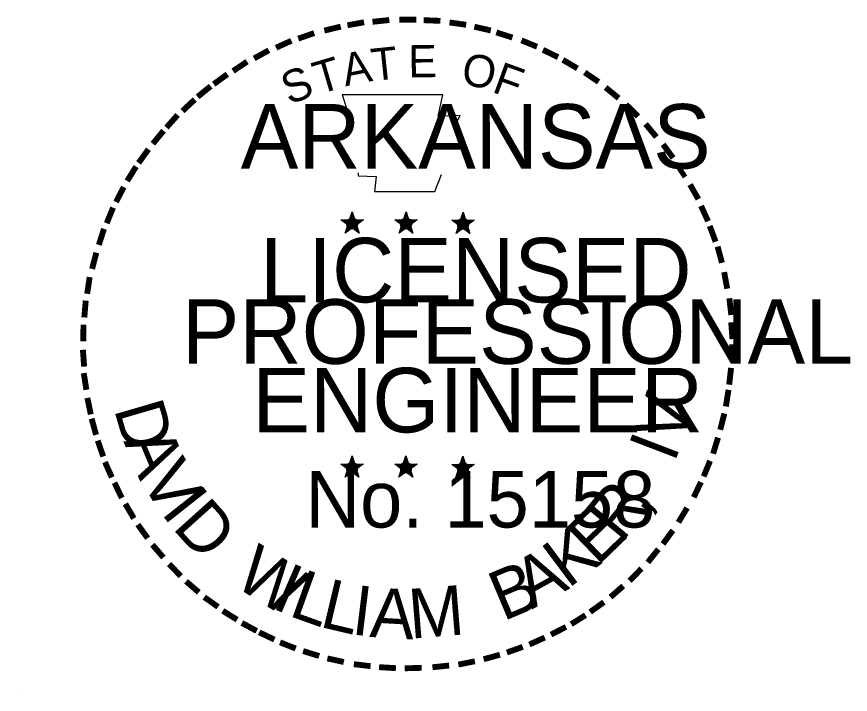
# Model space of a CAD drawing. Extents: x 28704 to 32542, y 50360 to 59122.
# Drawn here: x 30525.5 to 30658.7, y 58979.9 to 59088.2 of the extents above; entities that cross this region are included whole.
import ezdxf

# ---------------------------------------------------------------- set-up
doc = ezdxf.new("R2010")
doc.units = 0
doc.layers.add('R_Border Prem', color=7, linetype='Continuous')
doc.layers.add('R_Contours', color=7, linetype='Continuous')

msp = doc.modelspace()

# ---------------------------------------------------------------- linework, layer by layer
at = {"layer": 'R_Border Prem'}
for p, q in [((30579.13, 59057.02), (30578.92, 59055.72)), ((30579.13, 59055.14), (30579.13, 59057.02)), ((30579.13, 59057.02), (30579.38, 59055.73)), ((30587.74, 59057.02), (30587.53, 59055.72)), ((30587.74, 59055.14), (30587.74, 59057.02)), ((30587.74, 59057.02), (30587.99, 59055.73)), ((30596.84, 59056.96), (30596.63, 59055.66)), ((30596.84, 59055.08), (30596.84, 59056.96)), ((30596.84, 59056.96), (30597.09, 59055.67)), ((30577.33, 59055.71), (30579.13, 59055.14)), ((30577.33, 59055.71), (30578.64, 59055.48)), ((30577.33, 59055.71), (30578.55, 59055.08)), ((30578.02, 59053.61), (30579.13, 59055.14)), ((30578.02, 59053.61), (30578.67, 59054.87)), ((30578.02, 59053.61), (30579.12, 59054.73)), ((30580.23, 59053.61), (30579.12, 59054.71)), ((30580.92, 59055.71), (30579.13, 59055.14)), ((30580.23, 59053.61), (30579.13, 59055.14)), ((30580.92, 59055.71), (30579.44, 59055.46)), ((30580.23, 59053.61), (30579.52, 59055.11)), ((30580.92, 59055.71), (30579.87, 59055.18)), ((30585.94, 59055.71), (30587.74, 59055.14)), ((30585.94, 59055.71), (30587.25, 59055.48)), ((30585.94, 59055.71), (30587.16, 59055.08)), ((30586.63, 59053.61), (30587.74, 59055.14)), ((30586.63, 59053.61), (30587.28, 59054.87)), ((30586.63, 59053.61), (30587.73, 59054.73)), ((30588.84, 59053.61), (30587.73, 59054.71)), ((30589.53, 59055.71), (30587.74, 59055.14)), ((30588.84, 59053.61), (30587.74, 59055.14)), ((30589.53, 59055.71), (30588.06, 59055.46)), ((30588.84, 59053.61), (30588.13, 59055.11)), ((30589.53, 59055.71), (30588.48, 59055.18)), ((30595.04, 59055.65), (30596.84, 59055.08)), ((30595.04, 59055.65), (30596.34, 59055.42)), ((30595.04, 59055.65), (30596.26, 59055.02)), ((30595.72, 59053.55), (30596.84, 59055.08)), ((30595.72, 59053.55), (30596.37, 59054.8)), ((30595.72, 59053.55), (30596.83, 59054.66)), ((30597.94, 59053.55), (30596.83, 59054.65)), ((30598.63, 59055.65), (30596.84, 59055.08)), ((30597.94, 59053.55), (30596.84, 59055.08)), ((30598.63, 59055.65), (30597.15, 59055.4)), ((30597.94, 59053.55), (30597.23, 59055.05)), ((30598.63, 59055.65), (30597.57, 59055.12)), ((30579.11, 59017.97), (30578.9, 59016.67)), ((30579.11, 59016.09), (30579.11, 59017.97)), ((30579.11, 59017.97), (30579.36, 59016.68)), ((30587.72, 59017.97), (30587.5, 59016.67)), ((30587.72, 59016.09), (30587.72, 59017.97)), ((30587.72, 59017.97), (30587.97, 59016.68)), ((30596.83, 59017.92), (30596.62, 59016.62)), ((30596.83, 59016.04), (30596.83, 59017.92)), ((30596.83, 59017.92), (30597.08, 59016.63)), ((30577.31, 59016.66), (30579.11, 59016.09)), ((30577.31, 59016.66), (30578.61, 59016.43)), ((30577.31, 59016.66), (30578.53, 59016.03)), ((30578, 59014.56), (30579.11, 59016.09)), ((30578, 59014.56), (30578.65, 59015.82)), ((30580.9, 59016.66), (30579.11, 59016.09)), ((30580.21, 59014.56), (30579.11, 59016.09)), ((30580.9, 59016.66), (30579.42, 59016.41)), ((30580.21, 59014.56), (30579.5, 59016.06)), ((30580.9, 59016.66), (30579.85, 59016.14)), ((30585.92, 59016.66), (30587.72, 59016.09)), ((30585.92, 59016.66), (30587.22, 59016.43)), ((30585.92, 59016.66), (30587.14, 59016.03)), ((30586.6, 59014.56), (30587.72, 59016.09)), ((30586.6, 59014.56), (30587.25, 59015.82)), ((30589.5, 59016.66), (30587.72, 59016.09)), ((30588.81, 59014.56), (30587.72, 59016.09)), ((30589.5, 59016.66), (30588.03, 59016.41)), ((30588.81, 59014.56), (30588.11, 59016.06)), ((30589.5, 59016.66), (30588.45, 59016.14)), ((30595.03, 59016.61), (30596.83, 59016.04)), ((30595.03, 59016.61), (30596.33, 59016.38)), ((30595.03, 59016.61), (30596.25, 59015.98)), ((30595.71, 59014.51), (30596.83, 59016.04)), ((30598.62, 59016.61), (30596.83, 59016.04)), ((30597.92, 59014.51), (30596.83, 59016.04)), ((30598.62, 59016.61), (30597.14, 59016.36)), ((30597.92, 59014.51), (30597.22, 59016.01)), ((30598.62, 59016.61), (30597.56, 59016.09)), ((30578, 59014.56), (30579.1, 59015.68)), ((30580.21, 59014.56), (30579.1, 59015.66)), ((30586.6, 59014.56), (30587.71, 59015.68)), ((30588.81, 59014.56), (30587.71, 59015.66)), ((30595.71, 59014.51), (30596.36, 59015.77)), ((30595.71, 59014.51), (30596.82, 59015.63)), ((30597.92, 59014.51), (30596.82, 59015.61))]:
    msp.add_line(p, q, dxfattribs=at)
for points in [[(30577.54, 59075.71), (30578.93, 59071.44)], [(30595.65, 59070.95), (30596.38, 59072.42), (30592.85, 59072.29), (30593.61, 59075.71), (30577.54, 59075.71)], [(30580.08, 59063.21), (30580.08, 59062.76), (30582.98, 59062.67), (30582.7, 59060.23), (30592.35, 59060.23), (30593.38, 59062.99)], [(30579.13, 59057.02), (30580.23, 59053.61), (30577.33, 59055.71), (30580.92, 59055.71), (30578.02, 59053.61), (30579.13, 59057.02)], [(30587.74, 59057.02), (30588.84, 59053.61), (30585.94, 59055.71), (30589.53, 59055.71), (30586.63, 59053.61), (30587.74, 59057.02)], [(30596.84, 59056.96), (30597.94, 59053.55), (30595.04, 59055.65), (30598.63, 59055.65), (30595.72, 59053.55), (30596.84, 59056.96)], [(30579.11, 59017.97), (30580.21, 59014.56), (30577.31, 59016.66), (30580.9, 59016.66), (30578, 59014.56), (30579.11, 59017.97)], [(30587.72, 59017.97), (30588.81, 59014.56), (30585.92, 59016.66), (30589.5, 59016.66), (30586.6, 59014.56), (30587.72, 59017.97)], [(30596.83, 59017.92), (30597.92, 59014.51), (30595.03, 59016.61), (30598.62, 59016.61), (30595.71, 59014.51), (30596.83, 59017.92)]]:
    msp.add_lwpolyline(points, dxfattribs=at)
for centre, radius in [((30579.12, 59055.13), 0.888), ((30579.12, 59055.13), 0.745), ((30587.74, 59055.13), 0.888), ((30587.74, 59055.13), 0.745), ((30596.83, 59055.07), 0.888), ((30596.83, 59055.07), 0.745), ((30579.12, 59055.13), 0.597), ((30579.12, 59055.13), 0.511), ((30579.12, 59055.13), 0.385), ((30579.12, 59055.13), 0.255), ((30579.12, 59055.13), 0.153), ((30587.74, 59055.13), 0.597), ((30587.74, 59055.13), 0.511), ((30587.74, 59055.13), 0.385), ((30587.74, 59055.13), 0.255), ((30587.74, 59055.13), 0.153), ((30596.83, 59055.07), 0.597), ((30596.83, 59055.07), 0.511), ((30596.83, 59055.07), 0.385), ((30596.83, 59055.07), 0.255), ((30596.83, 59055.07), 0.153), ((30579.1, 59016.09), 0.888), ((30579.1, 59016.09), 0.745), ((30579.1, 59016.09), 0.597), ((30579.1, 59016.09), 0.511), ((30579.1, 59016.09), 0.385), ((30579.1, 59016.09), 0.255), ((30579.1, 59016.09), 0.153), ((30587.71, 59016.09), 0.888), ((30587.71, 59016.09), 0.745), ((30587.71, 59016.09), 0.597), ((30587.71, 59016.09), 0.511), ((30587.71, 59016.09), 0.385), ((30587.71, 59016.09), 0.255), ((30587.71, 59016.09), 0.153), ((30596.82, 59016.03), 0.888), ((30596.82, 59016.03), 0.745), ((30596.82, 59016.03), 0.597), ((30596.82, 59016.03), 0.511), ((30596.82, 59016.03), 0.385), ((30596.82, 59016.03), 0.255), ((30596.82, 59016.03), 0.153)]:
    msp.add_circle(centre, radius, dxfattribs=at)
at = {"layer": 'R_Contours'}
msp.add_line((30525.51, 58979.86), (30525.51, 58979.86), dxfattribs=at)

# ---------------------------------------------------------------- texts
at = {"layer": 'R_Border Prem'}
for s, height, rotation, p in [('-', 8.25, 10.2193, (30578.45, 59083.6)), ('-', 8.25, 5.8968, (30582.21, 59084.16)), ('-', 8.25, 0.1862, (30586.19, 59084.53)), ('-', 8.25, 357.743, (30589.92, 59084.47)), ('-', 8.25, 352.1617, (30593.75, 59084.18)), ('-', 8.25, 13.6302, (30574.95, 59082.76)), ('-', 8.25, 347.2049, (30597.46, 59083.59)), ('-', 8.25, 19.1761, (30571.09, 59081.52)), ('-', 8.25, 342.3362, (30600.73, 59082.79)), ('-', 8.25, 24.3072, (30567.82, 59080.13)), ('-', 8.25, 337.8551, (30604.52, 59081.64)), ('-', 8.25, 28.7918, (30564.55, 59078.5)), ('A', 5.16, 11.2132, (30578.03, 59077.05)), ('T', 5.16, 6.0228, (30582.41, 59077.9)), ('E', 5.16, 0.8323, (30588.11, 59078.47)), ('-', 8.25, 334.1211, (30607.78, 59080.24)), ('-', 8.25, 34.0636, (30561.47, 59076.59)), ('T', 5.16, 16.4036, (30573.77, 59075.75)), ('O', 5.16, 350.4515, (30596.38, 59077.39)), ('-', 8.25, 329.6409, (30610.76, 59078.79)), ('S', 5.16, 21.594, (30569.06, 59074.05)), ('F', 5.16, 340.0707, (30601.3, 59076.21)), ('-', 8.25, 36.2317, (30558.49, 59074.55)), ('-', 8.25, 325.8627, (30614.08, 59076.92)), ('-', 8.25, 38.9507, (30556.04, 59072.6)), ('-', 8.25, 320.5297, (30617.22, 59074.73)), ('-', 8.25, 42.9622, (30553.81, 59070.45)), ('-', 8.25, 315.5786, (30620.31, 59072.21)), ('-', 8.25, 48.4231, (30551.5, 59067.99)), ('-', 8.25, 309.8797, (30623.25, 59069.37)), ('-', 8.25, 50.6142, (30549.42, 59065.48)), ('-', 8.25, 306.6522, (30625.95, 59066.27)), ('-', 8.25, 54.2325, (30547.29, 59062.56)), ('-', 8.25, 58.0706, (30545.61, 59059.84)), ('-', 7.22, 303.6753, (30628.46, 59063.34)), ('-', 8.25, 62.8713, (30544, 59056.68)), ('-', 8.25, 299.6684, (30630.1, 59060.21)), ('-', 8.25, 67.7743, (30542.66, 59053.52)), ('-', 8.25, 294.6628, (30631.77, 59057.06)), ('-', 8.25, 72.3945, (30541.53, 59050.28)), ('-', 8.25, 290.5728, (30633.1, 59054.08)), ('-', 8.25, 75.461, (30540.52, 59046.59)), ('-', 8.25, 285.1233, (30634.31, 59051.09)), ('-', 8.25, 81.2013, (30539.84, 59042.92)), ('-', 8.25, 280.5493, (30635.34, 59047.26)), ('-', 8.25, 85.1863, (30539.45, 59039.36)), ('-', 8.25, 276.5962, (30636.17, 59043.3)), ('-', 8.25, 89.0622, (30539.32, 59035.74)), ('-', 8.25, 274.3301, (30636.48, 59039.58)), ('-', 8.25, 269.9407, (30636.66, 59036.32)), ('-', 8.25, 94.1959, (30539.5, 59032)), ('-', 8.25, 263.5172, (30636.56, 59032.89)), ('-', 8.25, 98.9479, (30539.87, 59028.56)), ('V', 7.94, 72.6573, (30631.73, 59019.51)), ('-', 8.25, 260.9953, (30636.19, 59029.52)), ('-', 8.25, 101.7149, (30540.57, 59024.78)), ('D', 7.94, 286.2848, (30541.02, 59025.5)), ('-', 8.25, 105.4578, (30541.4, 59021.72)), ('-', 8.25, 255.7626, (30635.63, 59026.02)), ('I', 7.94, 69.0301, (30630.59, 59016.73)), ('-', 8.25, 109.0874, (30542.51, 59018.46)), ('A', 7.94, 292.7835, (30542.53, 59020.33)), ('-', 8.25, 252.8681, (30634.69, 59022.31)), ('-', 8.25, 114.0643, (30543.82, 59015.39)), ('V', 7.94, 300.7936, (30545.18, 59014.25)), ('-', 8.25, 247.8887, (30633.54, 59018.84)), ('-', 8.25, 115.7289, (30545.39, 59012.2)), ('R', 7.94, 50.3651, (30622.08, 59003.9)), ('-', 8.25, 244.6197, (30632.19, 59015.6)), ('I', 7.94, 308.3502, (30548.44, 59008.9)), ('-', 8.25, 120.4471, (30547.23, 59009.18)), ('D', 7.94, 311.9774, (30550.24, 59006.5)), (',', 7.94, 57.4684, (30625.81, 59008.45)), ('E', 7.94, 44.0175, (30618.29, 59000.25)), ('-', 8.25, 239.0712, (30630.16, 59011.72)), ('-', 8.25, 125.8934, (30549.31, 59006.29)), ('K', 7.94, 36.9143, (30613.61, 58996.69)), ('-', 8.25, 233.8452, (30628.09, 59008.35)), ('-', 8.25, 130.7181, (30551.69, 59003.44)), ('W', 7.94, 328.0731, (30559.93, 58997.4)), ('-', 8.25, 231.2538, (30625.87, 59005.43)), ('B', 7.94, 22.8589, (30603.22, 58991.48)), ('A', 7.94, 28.9042, (30607.84, 58993.41)), ('-', 8.25, 134.2238, (30554.36, 59000.63)), ('I', 7.94, 336.6877, (30566.05, 58993.74)), ('-', 8.25, 225.7653, (30623.4, 59002.52)), ('L', 7.94, 340.3149, (30568.78, 58992.48)), ('-', 8.25, 138.9338, (30557.07, 58998.24)), ('L', 7.94, 346.6625, (30573.73, 58990.7)), ('I', 7.94, 353.0101, (30578.84, 58989.48)), ('M', 7.94, 4.6473, (30588.44, 58988.74)), ('-', 8.25, 221.0851, (30620.71, 58999.9)), ('A', 7.94, 356.6373, (30581.82, 58989.04)), ('-', 8.25, 144.6463, (30559.93, 58996.15)), ('-', 8.25, 215.7363, (30617.88, 58997.47)), ('-', 8.25, 148.0898, (30562.83, 58994.23)), ('-', 8.25, 212.2491, (30615.12, 58995.47)), ('-', 8.25, 151.5704, (30565.81, 58992.56)), ('-', 8.25, 207.3568, (30612.25, 58993.69)), ('-', 8.25, 154.6002, (30568.5, 58991.28)), ('-', 8.25, 204.2516, (30609.03, 58992.04)), ('-', 8.25, 158.5612, (30571.72, 58989.97)), ('-', 8.25, 199.4643, (30605.78, 58990.61)), ('-', 8.25, 162.7983, (30575.26, 58988.88)), ('-', 8.25, 195.4743, (30602.35, 58989.39)), ('-', 8.25, 167.5555, (30578.95, 58988.03)), ('-', 8.25, 173.1155, (30582.93, 58987.46)), ('-', 8.25, 191.2858, (30598.59, 58988.36)), ('-', 8.25, 176.5183, (30586.79, 58987.19)), ('-', 8.25, 181.5918, (30590.62, 58987.29)), ('-', 8.25, 185.8167, (30594.79, 58987.68))]:
    msp.add_text(s, height=height, rotation=rotation, dxfattribs=at).set_placement(p)
for s, height, p in [('ARKANSAS', 10.312, (30561.31, 59063.91)), ('LICENSED', 10.312, (30564.4, 59042.52)), ('PROFESSIONAL', 10.3125, (30551.9, 59032.7)), ('ENGINEER', 10.312, (30563.18, 59021.74)), ('No. 15158', 9.06, (30571.64, 59006.53)), ('AAMU', 0.000103, (30587.37, 58988.72))]:
    msp.add_text(s, height=height, dxfattribs=at).set_placement(p)

doc.saveas('drawing.dxf')
